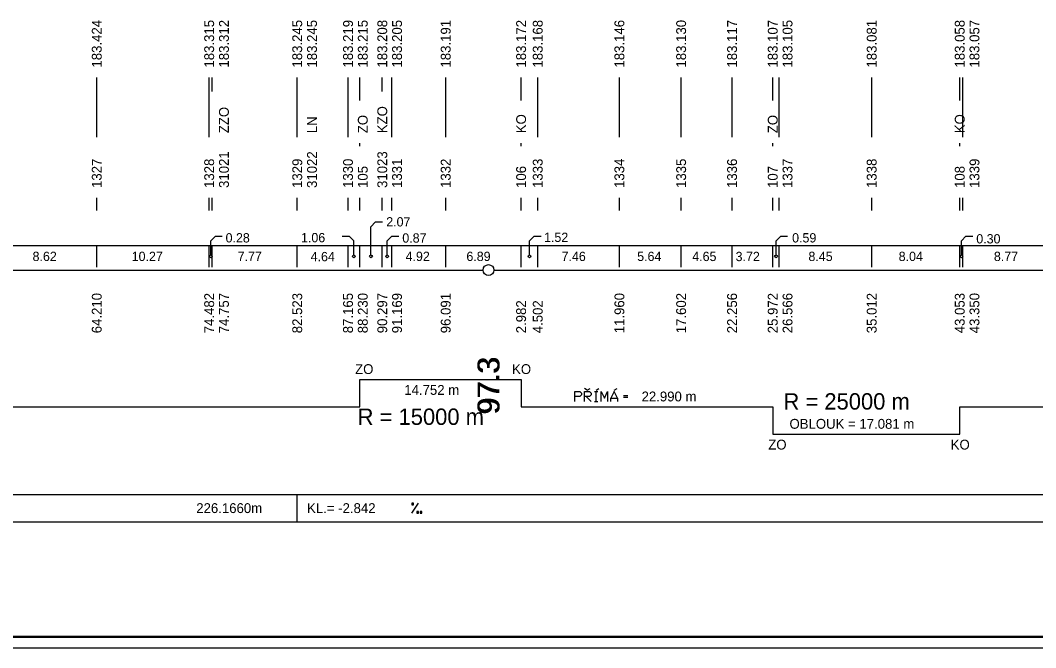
# Model space of a CAD drawing. Extents: x 0 to 10087, y -805 to 297.
# Drawn here: x 1894.5 to 2080, y 0 to 114.6 of the extents above; entities that cross this region are included whole.
import ezdxf

# ---------------------------------------------------------------- set-up
doc = ezdxf.new("R2010")
doc.units = 0
for name, color, linetype in [('CARKY_HODNOT', 7, 'Continuous'), ('KRIV1_CARA', 7, 'Continuous'), ('KRIV1_TEXT', 7, 'Continuous'), ('NIVELETA_CARA', 7, 'Continuous'), ('NIVELETA_TEXT', 7, 'Continuous'), ('PARAM_R', 7, 'Continuous'), ('RAM', 7, 'Continuous'), ('REZERVA', 7, 'Continuous'), ('STAN_CARA', 7, 'Continuous'), ('STAN_PAS', 7, 'Continuous'), ('STAN_TEXT', 7, 'Continuous'), ('TEXT', 7, 'Continuous'), ('TXT_C_BODU', 7, 'Continuous')]:
    doc.layers.add(name, color=color, linetype=linetype)

msp = doc.modelspace()

# ---------------------------------------------------------------- linework, layer by layer
at = {"layer": 'CARKY_HODNOT'}
for p, q in [((1908.42, 93.3), (1908.42, 104.2)), ((1928.96, 93.3), (1928.96, 104.2)), ((1929.51, 101.65), (1929.51, 104.2)), ((1945.05, 93.3), (1945.05, 104.2)), ((1945.05, 100), (1945.05, 104.2)), ((1954.33, 93.3), (1954.33, 104.2)), ((1956.46, 100), (1956.46, 104.2)), ((1960.59, 101.65), (1960.59, 104.2)), ((1962.34, 93.3), (1962.34, 104.2)), ((1972.18, 93.3), (1972.18, 104.2)), ((1985.96, 100), (1985.96, 104.2)), ((1989, 93.3), (1989, 104.2)), ((2003.92, 93.3), (2003.92, 104.2)), ((2015.2, 93.3), (2015.2, 104.2)), ((2024.51, 93.3), (2024.51, 104.2)), ((2031.94, 100), (2031.94, 104.2)), ((2033.13, 93.3), (2033.13, 104.2)), ((2050.02, 93.3), (2050.02, 104.2)), ((2066.11, 100), (2066.11, 104.2)), ((2066.7, 93.3), (2066.7, 104.2)), ((1956.46, 91.65), (1956.46, 92.2)), ((1985.96, 91.65), (1985.96, 92.2)), ((2031.94, 91.65), (2031.94, 92.2)), ((2066.11, 91.65), (2066.11, 92.2)), ((1908.42, 79.9), (1908.42, 82.2)), ((1928.96, 79.9), (1928.96, 82.2)), ((1929.51, 79.9), (1929.51, 82.2)), ((1945.05, 79.9), (1945.05, 82.2)), ((1945.05, 79.9), (1945.05, 82.2)), ((1954.33, 79.9), (1954.33, 82.2)), ((1956.46, 79.9), (1956.46, 82.2)), ((1960.59, 79.9), (1960.59, 82.2)), ((1962.34, 79.9), (1962.34, 82.2)), ((1972.18, 79.9), (1972.18, 82.2)), ((1985.96, 79.9), (1985.96, 82.2)), ((1989, 79.9), (1989, 82.2)), ((2003.92, 79.9), (2003.92, 82.2)), ((2015.2, 79.9), (2015.2, 82.2)), ((2024.51, 79.9), (2024.51, 82.2)), ((2031.94, 79.9), (2031.94, 82.2)), ((2033.13, 79.9), (2033.13, 82.2)), ((2050.02, 79.9), (2050.02, 82.2)), ((2066.11, 79.9), (2066.11, 82.2)), ((2066.7, 79.9), (2066.7, 82.2))]:
    msp.add_line(p, q, dxfattribs=at)
at = {"layer": 'KRIV1_CARA'}
for p, q in [((1956.46, 44), (1956.46, 49)), ((1956.46, 49), (1985.96, 49)), ((1985.96, 49), (1985.96, 44)), ((1094.43, 44), (1956.46, 44)), ((1985.96, 44), (2031.94, 44)), ((2031.94, 44), (2031.94, 39)), ((2066.11, 39), (2066.11, 44)), ((2066.11, 44), (2477.23, 44)), ((2031.94, 39), (2066.11, 39))]:
    msp.add_line(p, q, dxfattribs=at)
at = {"layer": 'KRIV1_TEXT'}
for p, q in [((1995.75, 45), (1995.75, 46.8)), ((1995.75, 46.8), (1996.67, 46.8)), ((1996.67, 46.8), (1996.97, 46.49)), ((1996.97, 46.49), (1996.97, 46.2)), ((1998.04, 47.03), (1997.53, 47.37)), ((1997.55, 45), (1997.55, 46.8)), ((1997.55, 46.8), (1998.46, 46.8)), ((1998.04, 47.03), (1998.55, 47.37)), ((1998.46, 46.8), (1998.76, 46.51)), ((1998.76, 46.51), (1998.76, 46.2)), ((1999.39, 46.79), (1999.96, 46.79)), ((1999.67, 47.03), (2000.18, 47.37)), ((1999.68, 45), (1999.68, 46.79)), ((2000.56, 45), (2000.56, 46.79)), ((2000.56, 46.79), (2001.18, 45.6)), ((2001.18, 45.6), (2001.76, 46.79)), ((2001.76, 46.79), (2001.76, 45)), ((2002.97, 46.81), (2002.36, 45.6)), ((2003.56, 45.6), (2002.97, 46.81)), ((2002.99, 47.03), (2003.5, 47.37)), ((1996.66, 45.9), (1995.75, 45.9)), ((1996.97, 46.2), (1996.66, 45.9)), ((1998.46, 45.9), (1997.55, 45.9)), ((1997.85, 45.9), (1998.76, 45)), ((1998.76, 46.2), (1998.46, 45.9)), ((1999.39, 45), (1999.96, 45)), ((2002.36, 45), (2002.36, 45.6)), ((2002.36, 45.6), (2003.56, 45.6)), ((2003.56, 45.6), (2003.56, 45)), ((2004.68, 46.07), (2005.49, 46.07)), ((2004.68, 45.75), (2005.49, 45.75))]:
    msp.add_line(p, q, dxfattribs=at)
at = {"layer": 'NIVELETA_CARA'}
for p, q in [((500, 28), (8321.33, 28)), ((1945.05, 23), (1945.05, 28)), ((500, 23), (8321.33, 23))]:
    msp.add_line(p, q, dxfattribs=at)
at = {"layer": 'NIVELETA_TEXT'}
for p, q in [((1966.01, 24.6), (1967.2, 26.4)), ((1966.01, 26.4), (1966.01, 26.1)), ((1966.3, 26.4), (1966.01, 26.4)), ((1966.01, 26.4), (1966.01, 26.39)), ((1966.01, 26.1), (1966.3, 26.1)), ((1966.3, 26.1), (1966.3, 26.4)), ((1966.92, 24.9), (1966.92, 24.6)), ((1967.21, 24.9), (1966.92, 24.9)), ((1966.92, 24.9), (1966.92, 24.89)), ((1966.92, 24.6), (1967.21, 24.6)), ((1967.21, 24.6), (1967.21, 24.9)), ((1967.53, 24.9), (1967.53, 24.6)), ((1967.83, 24.9), (1967.53, 24.9)), ((1967.53, 24.9), (1967.53, 24.89)), ((1967.53, 24.6), (1967.83, 24.6)), ((1967.83, 24.6), (1967.83, 24.9))]:
    msp.add_line(p, q, dxfattribs=at)
at = {"layer": 'RAM'}
for p, q in [((2, 2.1), (8634.33, 2.1)), ((2, 2), (8634.33, 2)), ((2, 1.9), (8634.33, 1.9)), ((0, 0), (8636.33, 0))]:
    msp.add_line(p, q, dxfattribs=at)
at = {"layer": 'REZERVA'}
msp.add_circle((1980, 69), 1, dxfattribs=at)
at = {"layer": 'STAN_CARA'}
for p, q in [((1781, 69), (1979, 69)), ((1981, 69), (2179, 69))]:
    msp.add_line(p, q, dxfattribs=at)
at = {"layer": 'STAN_PAS'}
for p, q in [((1958.53, 76.92), (1959.38, 77.78)), ((1958.53, 71.75), (1958.53, 76.9)), ((1959.38, 77.78), (1960.65, 77.78)), ((1929.24, 74.35), (1930.09, 75.2)), ((1929.24, 71.75), (1929.24, 74.35)), ((1930.09, 75.2), (1931.36, 75.2)), ((1953.27, 75.2), (1954.54, 75.2)), ((1955.39, 74.35), (1954.54, 75.2)), ((1955.39, 71.75), (1955.39, 74.35)), ((1961.47, 74.35), (1962.32, 75.2)), ((1961.47, 71.75), (1961.47, 74.35)), ((1962.32, 75.2), (1963.59, 75.2)), ((1987.48, 74.35), (1988.33, 75.2)), ((1987.48, 71.75), (1987.48, 74.35)), ((1988.33, 75.2), (1989.61, 75.2)), ((2032.54, 74.35), (2033.39, 75.2)), ((2032.54, 71.75), (2032.54, 74.35)), ((2033.39, 75.2), (2034.66, 75.2)), ((2066.4, 74.35), (2067.25, 75.2)), ((2066.4, 71.75), (2066.4, 74.35)), ((2067.25, 75.2), (2068.53, 75.2)), ((300, 73.5), (8321.33, 73.5)), ((1908.42, 69.5), (1908.42, 73.5)), ((1928.96, 69.5), (1928.96, 73.5)), ((1929.51, 69.5), (1929.51, 73.5)), ((1945.05, 69.5), (1945.05, 73.5)), ((1945.05, 69.5), (1945.05, 73.5)), ((1954.33, 69.5), (1954.33, 73.5)), ((1956.46, 69.5), (1956.46, 73.5)), ((1960.59, 69.5), (1960.59, 73.5)), ((1962.34, 69.5), (1962.34, 73.5)), ((1972.18, 69.5), (1972.18, 73.5)), ((1985.96, 69.5), (1985.96, 73.5)), ((1989, 69.5), (1989, 73.5)), ((2003.92, 69.5), (2003.92, 73.5)), ((2015.2, 69.5), (2015.2, 73.5)), ((2024.51, 69.5), (2024.51, 73.5)), ((2031.94, 69.5), (2031.94, 73.5)), ((2033.13, 69.5), (2033.13, 73.5)), ((2050.02, 69.5), (2050.02, 73.5)), ((2066.11, 69.5), (2066.11, 73.5)), ((2066.7, 69.5), (2066.7, 73.5))]:
    msp.add_line(p, q, dxfattribs=at)
for centre in [(1929.24, 71.5), (1955.39, 71.5), (1958.53, 71.5), (1961.47, 71.5), (1987.48, 71.5), (2032.54, 71.5), (2066.4, 71.5)]:
    msp.add_circle(centre, 0.25, dxfattribs=at)

# ---------------------------------------------------------------- texts
at = {"layer": 'KRIV1_TEXT'}
for s, p in [('ZO', (1955.63, 50)), ('KO', (1984.31, 50)), ('14.752 m', (1964.61, 46.2)), (' 22.990 m', (2007.3, 45)), ('OBLOUK = 17.081 m', (2035, 40)), ('ZO', (2031.12, 36.2)), ('KO', (2064.46, 36.2))]:
    msp.add_text(s, height=1.8, dxfattribs=at).set_placement(p)
at = {"layer": 'NIVELETA_TEXT'}
for s, p in [('226.1660m', (1926.6, 24.6)), ('KL.= -2.842', (1946.85, 24.6))]:
    msp.add_text(s, height=1.8, dxfattribs=at).set_placement(p)
at = {"layer": 'PARAM_R'}
for s, p in [('R = 25000 m', (2033.9, 43.5)), ('R = 15000 m', (1956.09, 40.7))]:
    msp.add_text(s, height=3, dxfattribs=at).set_placement(p)
at = {"layer": 'STAN_TEXT'}
for s, p in [('2.07', (1961.31, 76.96)), ('0.28', (1931.96, 74.04)), ('1.06', (1945.74, 74.07)), ('0.87', (1964.25, 74.01)), ('1.52', (1990.15, 74.13)), ('0.59', (2035.48, 74.04)), ('0.30', (2069.13, 73.86)), ('8.62', (1896.69, 70.65)), ('10.27', (1914.8, 70.65)), ('4.92', (1964.85, 70.65)), ('6.89', (1975.96, 70.65)), ('7.46', (1993.35, 70.65)), ('5.64', (2007.17, 70.65)), ('4.65', (2017.23, 70.64)), ('8.45', (2038.46, 70.65)), ('8.04', (2054.95, 70.65)), ('8.77', (2072.35, 70.65)), ('7.77', (1934.16, 70.65)), ('4.64', (1947.5, 70.61)), ('3.72', (2025.15, 70.63))]:
    msp.add_text(s, height=1.7, dxfattribs=at).set_placement(p)
for s, height, p in [('64.210', 1.8, (1909.32, 57.45)), ('74.482', 1.8, (1929.86, 57.45)), ('74.757', 1.8, (1932.56, 57.45)), ('82.523', 1.8, (1945.95, 57.45)), ('87.165', 1.8, (1955.23, 57.45)), ('88.230', 1.8, (1957.93, 57.45)), ('90.297', 1.8, (1961.49, 57.45)), ('91.169', 1.8, (1964.19, 57.45)), ('96.091', 1.8, (1973.08, 57.45)), ('2.982', 1.8, (1986.86, 57.45)), ('4.502', 1.8, (1989.9, 57.45)), ('11.960', 1.8, (2004.82, 57.45)), ('17.602', 1.8, (2016.1, 57.45)), ('22.256', 1.8, (2025.41, 57.45)), ('25.972', 1.8, (2032.84, 57.45)), ('26.566', 1.8, (2035.54, 57.45)), ('35.012', 1.8, (2050.92, 57.45)), ('43.053', 1.8, (2067.01, 57.45)), ('43.350', 1.8, (2069.7, 57.45)), ('    97.3', 4, (1982, 36.84)), ('    97.3', 4, (1982, 36.74)), ('    97.3', 4, (1982, 36.64))]:
    msp.add_text(s, height=height, rotation=90, dxfattribs=at).set_placement(p)
at = {"layer": 'TEXT'}
for s, p in [('183.424', (1909.32, 106)), ('183.315', (1929.86, 106)), ('183.312', (1932.56, 106)), ('183.245', (1945.95, 106)), ('183.245', (1948.65, 106)), ('183.219', (1955.23, 106)), ('183.215', (1957.93, 106)), ('183.208', (1961.49, 106)), ('183.205', (1964.19, 106)), ('183.191', (1973.08, 106)), ('183.172', (1986.86, 106)), ('183.168', (1989.9, 106)), ('183.146', (2004.82, 106)), ('183.130', (2016.1, 106)), ('183.117', (2025.41, 106)), ('183.107', (2032.84, 106)), ('183.105', (2035.54, 106)), ('183.081', (2050.92, 106)), ('183.058', (2067.01, 106)), ('183.057', (2069.7, 106)), ('ZZO', (1932.56, 94)), ('KZO', (1961.49, 94)), ('LN', (1948.65, 94)), ('ZO', (1957.93, 94)), ('KO', (1986.86, 94)), ('ZO', (2032.84, 94)), ('KO', (2067.01, 94))]:
    msp.add_text(s, height=1.8, rotation=90, dxfattribs=at).set_placement(p)
at = {"layer": 'TXT_C_BODU'}
for s, p in [('1327', (1909.32, 84)), ('1328', (1929.86, 84)), ('31021', (1932.56, 84)), ('1329', (1945.95, 84)), ('31022', (1948.65, 84)), ('1330', (1955.23, 84)), ('31023', (1961.49, 84)), ('1331', (1964.19, 84)), ('1332', (1973.08, 84)), ('1333', (1989.9, 84)), ('1334', (2004.82, 84)), ('1335', (2016.1, 84)), ('1336', (2025.41, 84)), ('1337', (2035.54, 84)), ('1338', (2050.92, 84)), ('1339', (2069.7, 84)), ('105', (1957.93, 84)), ('106', (1986.86, 84)), ('107', (2032.84, 84)), ('108', (2067.01, 84))]:
    msp.add_text(s, height=1.8, rotation=90, dxfattribs=at).set_placement(p)

doc.saveas('drawing.dxf')
